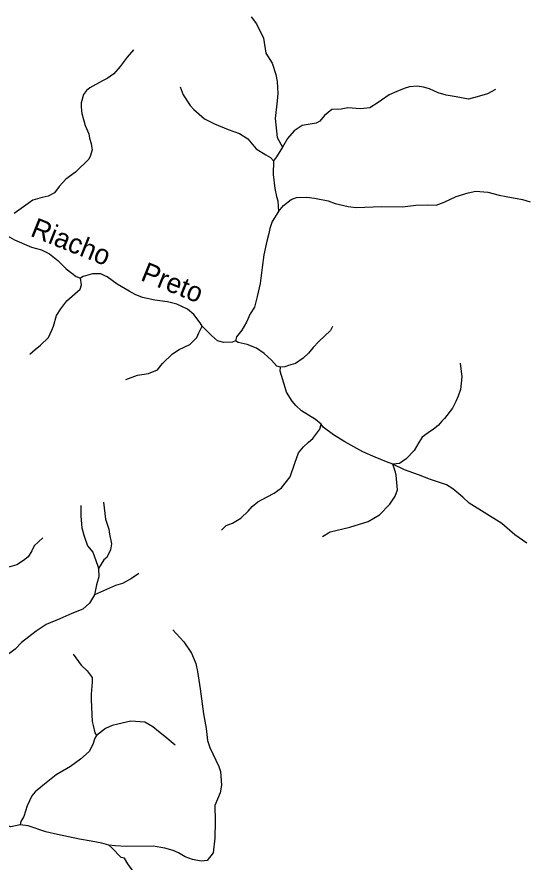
# Model space of a CAD drawing. Extents: x 717.8 to 772.7, y 8672.2 to 8728.
# Drawn here: x 767.35 to 772.55, y 8700.84 to 8709.4 of the extents above; entities that cross this region are included whole.
import ezdxf
from ezdxf.enums import TextEntityAlignment as Align

# ---------------------------------------------------------------- set-up
doc = ezdxf.new("R2010")
doc.units = 0
doc.header["$LTSCALE"] = 0.08
doc.linetypes.add('LONG_DASHED', pattern=[7.5, 6, -1.5])
doc.layers.add('61', color=7, linetype='Continuous')
doc.layers.add('9', color=7, linetype='LONG_DASHED', lineweight=25)

msp = doc.modelspace()

# ---------------------------------------------------------------- linework, layer by layer
at = {"layer": '9'}
for points in [[(769.7288, 8709.3983), (769.7795, 8709.3265), (769.8523, 8709.1826), (769.8743, 8709.0313), (769.9396, 8708.9308), (769.976, 8708.8156), (769.9906, 8708.7437), (769.998, 8708.6212), (769.9909, 8708.5492), (769.9695, 8708.3692), (769.9913, 8708.1772), (770.0445, 8708.0794)], [(768.5334, 8709.0664), (768.4708, 8708.9896), (768.3989, 8708.8957), (768.3364, 8708.823), (768.2681, 8708.7758), (768.2189, 8708.7512), (768.0935, 8708.6818), (768.059, 8708.6515), (768.0274, 8708.6121), (768.0029, 8708.5273), (768.003, 8708.4842), (768.0104, 8708.4193), (768.0436, 8708.2995), (768.0823, 8708.2136), (768.0901, 8708.1716), (768.104, 8708.1179), (768.1097, 8708.0933), (768.1147, 8708.0526), (768.0974, 8707.9949), (768.083, 8707.9589), (767.9465, 8707.828), (767.8472, 8707.7546), (767.7811, 8707.6823), (767.734, 8707.6177), (767.6685, 8707.5818), (767.608, 8707.5691), (767.5144, 8707.5431), (767.4419, 8707.4931), (767.3239, 8707.4081)], [(769.0083, 8708.6899), (769.0373, 8708.6108), (769.1097, 8708.503), (769.1458, 8708.46), (769.2542, 8708.3667), (769.3554, 8708.3166), (769.4926, 8708.2596), (769.6083, 8708.2167), (769.6942, 8708.1639), (769.7776, 8708.062), (769.8758, 8708.0018), (769.9244, 8707.9753), (769.9539, 8707.9412)], [(772.2041, 8708.662), (772.1226, 8708.6198), (772.0182, 8708.5885), (771.9288, 8708.5647), (771.8035, 8708.5884), (771.7027, 8708.6069), (771.6235, 8708.6292), (771.5353, 8708.6687), (771.4724, 8708.6867), (771.4097, 8708.6955), (771.3319, 8708.6898), (771.278, 8708.6743), (771.2047, 8708.6442), (771.1269, 8708.608), (771.0156, 8708.5311), (770.9291, 8708.4772), (770.8363, 8708.4676), (770.7073, 8708.4764), (770.6402, 8708.4658), (770.5439, 8708.4614), (770.4689, 8708.3995), (770.422, 8708.3412), (770.3857, 8708.3236), (770.2445, 8708.2981), (770.1646, 8708.244), (770.0939, 8708.1661), (770.0445, 8708.0794)], [(770.0445, 8708.0794), (769.9843, 8707.9805), (769.9539, 8707.9412)], [(769.9539, 8707.9412), (769.9489, 8707.8032), (769.9681, 8707.6622), (769.984, 8707.5788), (769.9972, 8707.5345), (770.0057, 8707.4282)], [(770.0057, 8707.4282), (770.056, 8707.4891), (770.1315, 8707.5484), (770.1883, 8707.5702), (770.2904, 8707.5734), (770.3691, 8707.5615), (770.5079, 8707.5362), (770.5787, 8707.5104), (770.7097, 8707.4801), (770.7913, 8707.4703), (771.0528, 8707.4797), (771.2616, 8707.4759), (771.3965, 8707.4932), (771.5156, 8707.4951), (771.6016, 8707.4932), (771.6836, 8707.5223), (771.8051, 8707.5806), (771.9259, 8707.6156), (772.006, 8707.6335), (772.1263, 8707.6235), (772.2421, 8707.5938), (772.3102, 8707.5785), (772.4761, 8707.5502), (772.5546, 8707.525)], [(770.0057, 8707.4282), (769.9416, 8707.3255), (769.9159, 8707.2555), (769.9054, 8707.2041), (769.8851, 8707.1279), (769.855, 8706.9888), (769.8371, 8706.8605), (769.8189, 8706.6986), (769.7888, 8706.5674), (769.76, 8706.4597), (769.7186, 8706.3915), (769.6805, 8706.3061), (769.6324, 8706.2278), (769.5795, 8706.1584), (769.5687, 8706.1177)], [(767.1119, 8707.2603), (767.2556, 8707.1829), (767.3288, 8707.1418), (767.5008, 8707.0682), (767.6009, 8707.0406), (767.684, 8706.9984), (767.7659, 8706.9336)], [(767.7659, 8706.9336), (767.8532, 8706.8479), (767.9091, 8706.8036), (767.9535, 8706.7692), (767.9979, 8706.7524)], [(768.2028, 8706.7964), (768.1195, 8706.7964), (768.0709, 8706.7845), (768.0243, 8706.7701), (767.9979, 8706.7524)], [(769.2299, 8706.2667), (769.2104, 8706.302), (769.146, 8706.3855), (769.0807, 8706.4403), (768.9724, 8706.4898), (768.878, 8706.513), (768.7502, 8706.5298), (768.6273, 8706.5561), (768.5518, 8706.5883), (768.4891, 8706.62), (768.3674, 8706.6911), (768.2668, 8706.7664), (768.2442, 8706.777), (768.2028, 8706.7964)], [(767.4846, 8705.985), (767.5387, 8706.0317), (767.5928, 8706.0755), (767.6744, 8706.1521), (767.7083, 8706.2282), (767.7248, 8706.2677), (767.7542, 8706.3745), (767.7985, 8706.4412), (767.8596, 8706.5238), (767.9949, 8706.6422), (768.0072, 8706.6868), (767.9979, 8706.7524)], [(768.4574, 8705.7272), (768.5755, 8705.7721), (768.6864, 8705.7878), (768.7771, 8705.8255), (768.8297, 8705.8878), (768.9287, 8705.9886), (768.9972, 8706.0296), (769.1068, 8706.0829), (769.1767, 8706.1519), (769.1977, 8706.1981), (769.2299, 8706.2667)], [(769.5687, 8706.1177), (769.538, 8706.1061), (769.4487, 8706.1021), (769.3853, 8706.1185), (769.3242, 8706.1713), (769.2299, 8706.2667)], [(770.5527, 8706.2625), (770.5299, 8706.2238), (770.4137, 8706.1109), (770.3559, 8706.0507), (770.3088, 8705.9933), (770.2533, 8705.9439), (770.1758, 8705.8897), (770.1059, 8705.8673), (770.0676, 8705.8547), (770.0237, 8705.8533)], [(770.0237, 8705.8533), (769.9888, 8705.8617), (769.934, 8705.9228), (769.8586, 8705.99), (769.7812, 8706.0455), (769.6873, 8706.0809), (769.5947, 8706.1028), (769.5687, 8706.1177)], [(770.4374, 8705.2752), (770.3783, 8705.3211), (770.2384, 8705.4088), (770.18, 8705.4653), (770.1424, 8705.5064), (770.0855, 8705.5993), (770.0731, 8705.6453), (770.0195, 8705.8128), (770.0237, 8705.8533)], [(771.8456, 8705.8932), (771.8614, 8705.7551), (771.8488, 8705.6255), (771.8246, 8705.5595), (771.8031, 8705.504), (771.7667, 8705.4377), (771.6878, 8705.3308), (771.6586, 8705.3048), (771.6222, 8705.2628), (771.5741, 8705.2259), (771.5197, 8705.1868), (771.461, 8705.1419), (771.4263, 8705.0906), (771.3783, 8705.0099), (771.2985, 8704.9227), (771.2317, 8704.8766), (771.1623, 8704.8702)], [(769.4265, 8704.2018), (769.4745, 8704.2475), (769.538, 8704.2732), (769.6238, 8704.3222), (769.6983, 8704.3939), (769.7365, 8704.441), (769.7939, 8704.4872), (769.8891, 8704.5399), (769.9586, 8704.5774), (770.035, 8704.6303), (770.1218, 8704.7405), (770.1688, 8704.8796), (770.2071, 8704.9864), (770.2565, 8705.0442), (770.3097, 8705.0942), (770.3531, 8705.1292), (770.4244, 8705.2239), (770.4374, 8705.2752)], [(771.1623, 8704.8702), (771.0999, 8704.8926), (770.9852, 8704.942), (770.8592, 8704.9962), (770.6766, 8705.0957), (770.5606, 8705.1683), (770.4566, 8705.2439), (770.4374, 8705.2752)], [(770.4517, 8704.1362), (770.528, 8704.1839), (770.7288, 8704.2311), (770.9116, 8704.2888), (771.0268, 8704.356), (771.1325, 8704.4653), (771.1856, 8704.5477), (771.2092, 8704.6102), (771.1966, 8704.7593), (771.1894, 8704.7879), (771.1623, 8704.8702)], [(772.5217, 8704.0707), (772.3996, 8704.1533), (772.2664, 8704.269), (771.9366, 8704.476), (771.871, 8704.5344), (771.7727, 8704.6204), (771.7061, 8704.6594), (771.5452, 8704.7147), (771.4222, 8704.7619), (771.2819, 8704.8141), (771.1623, 8704.8702)], [(768.2311, 8704.4867), (768.2492, 8704.3147), (768.2828, 8704.2125), (768.2926, 8704.1611), (768.3114, 8704.0627), (768.302, 8704.0017), (768.2644, 8703.9266), (768.235, 8703.9021), (768.1796, 8703.814)], [(768.001, 8704.4511), (768.0009, 8704.3433), (768.0103, 8704.2262), (768.0346, 8704.1414), (768.0667, 8704.0435), (768.1212, 8703.9794), (768.1702, 8703.8468), (768.1796, 8703.814)], [(767.6154, 8704.1247), (767.5289, 8704.0419), (767.5031, 8703.9927), (767.4651, 8703.9324), (767.419, 8703.8931), (767.3517, 8703.8518), (767.256, 8703.8247), (767.1629, 8703.82), (767.084, 8703.7962), (766.9728, 8703.813), (766.9134, 8703.8324), (766.8748, 8703.8617)], [(768.1796, 8703.814), (768.1843, 8703.7296), (768.1608, 8703.6499), (768.1393, 8703.5465)], [(768.5895, 8703.7633), (768.5144, 8703.7133), (768.4227, 8703.6633), (768.3514, 8703.6419), (768.1393, 8703.5465)], [(768.1393, 8703.5465), (768.0876, 8703.4634), (768.0217, 8703.4014), (767.9092, 8703.3587), (767.7894, 8703.3051), (767.6478, 8703.2468), (767.5479, 8703.1802), (767.3979, 8703.0637), (767.3341, 8702.9977), (767.2403, 8702.926), (767.1201, 8702.8587), (767.0218, 8702.8212), (766.9527, 8702.8112)], [(768.9335, 8703.1916), (769.0461, 8703.0722), (769.1226, 8702.9562), (769.1663, 8702.8528), (769.1831, 8702.7695), (769.2115, 8702.5964), (769.2452, 8702.3438), (769.2704, 8702.1942), (769.2839, 8702.0725), (769.3074, 8702.0027), (769.399, 8701.8093), (769.415, 8701.7572), (769.4251, 8701.6201), (769.4128, 8701.541), (769.3587, 8701.4142), (769.3637, 8701.2569), (769.3587, 8701.0844), (769.341, 8700.9364), (769.2814, 8700.8565), (769.2216, 8700.8508), (769.1326, 8700.8666), (769.057, 8700.8961), (768.9914, 8700.9347), (768.9368, 8700.9591), (768.8528, 8700.9835), (768.7334, 8701.0011), (768.4601, 8701.0003), (768.3501, 8701.0075), (768.2855, 8701.014)], [(767.9242, 8702.9448), (768.0035, 8702.8364), (768.0649, 8702.7776), (768.1144, 8702.7108), (768.1155, 8702.6613), (768.1067, 8702.5429), (768.1056, 8702.4826), (768.1154, 8702.266), (768.1255, 8702.2256), (768.1422, 8702.149), (768.158, 8702.1238)], [(768.9577, 8702.0249), (768.8522, 8702.1113), (768.7876, 8702.1651), (768.7305, 8702.2124), (768.6498, 8702.2575), (768.5082, 8702.2668), (768.3773, 8702.2374), (768.3194, 8702.2251), (768.2505, 8702.1923), (768.158, 8702.1238)], [(768.158, 8702.1238), (768.1419, 8702.0946), (768.1237, 8702.0303), (768.084, 8701.9605), (767.9966, 8701.8834), (767.8945, 8701.8106), (767.751, 8701.7232), (767.617, 8701.6161), (767.5369, 8701.553), (767.5036, 8701.5133), (767.4568, 8701.4123), (767.4214, 8701.3033), (767.3909, 8701.2535), (767.3842, 8701.217)], [(767.3842, 8701.217), (767.2923, 8701.1967), (767.2377, 8701.2161), (767.1192, 8701.3095), (767.0512, 8701.3423), (766.9566, 8701.3795), (766.8435, 8701.3938), (766.7837, 8701.3787), (766.7324, 8701.3304)], [(768.2855, 8701.014), (768.2135, 8701.0339), (768.1069, 8701.053), (767.9858, 8701.0742), (767.7633, 8701.1196), (767.6448, 8701.1484), (767.4656, 8701.208), (767.3842, 8701.217)], [(769.4305, 8700.1491), (769.2842, 8700.1939), (769.0451, 8700.2496), (768.9852, 8700.279), (768.8659, 8700.3643), (768.7872, 8700.4645), (768.6633, 8700.5745), (768.5828, 8700.6794), (768.4757, 8700.8226), (768.4437, 8700.8809), (768.4086, 8700.8887), (768.3161, 8700.9848), (768.2855, 8701.014)]]:
    msp.add_lwpolyline(points, dxfattribs=at)

# ---------------------------------------------------------------- texts
at = {"layer": '61'}
msp.add_text('Riacho     Preto', height=0.2, rotation=338.13, dxfattribs=at).set_placement((768.3343, 8706.841), align=Align.CENTER)

doc.saveas('drawing.dxf')
